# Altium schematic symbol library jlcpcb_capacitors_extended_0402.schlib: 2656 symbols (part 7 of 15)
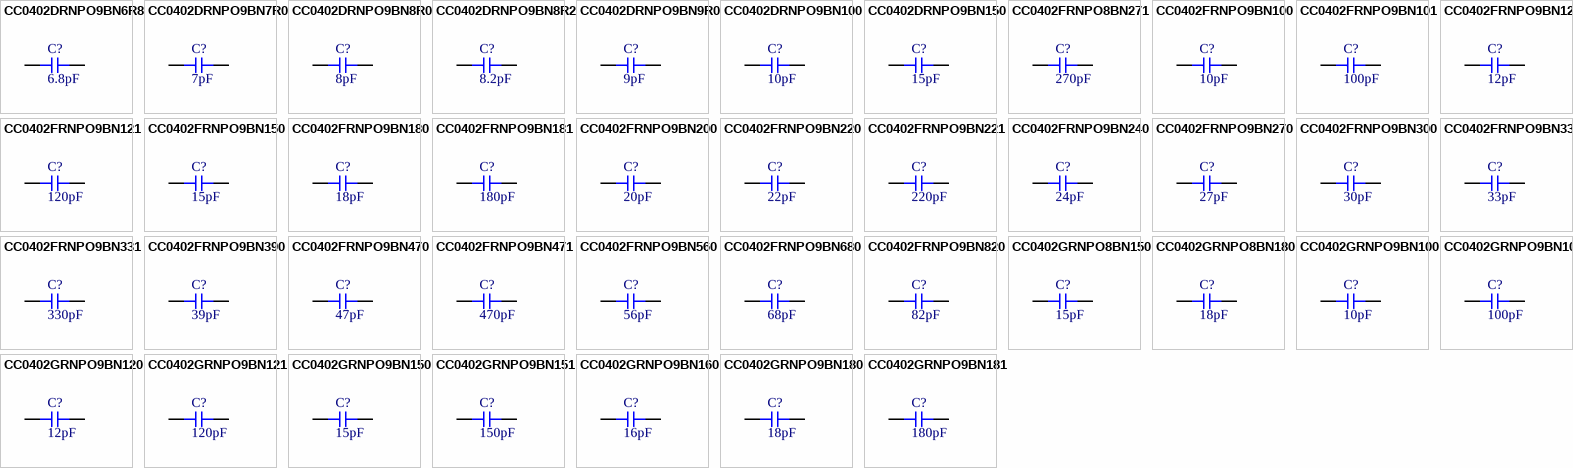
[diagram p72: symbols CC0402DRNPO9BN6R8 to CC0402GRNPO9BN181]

## CC0402FRNPO9BN180
designator C?  Capacitance: 18pF  (hidden comment: *)
Capacitor, Ceramic (MLCC), 18pF, ±1pF, 50V, NP0, ±1pF, SMD 0402; Manufacturer: YAGEO; Manufacturer Part Number: CC0402FRNPO9BN180
footprint CAP-0402 (0402 (1005M) Capacitor)
pins: 1, 2

## CC0402FRNPO9BN181
designator C?  Capacitance: 180pF  (hidden comment: *)
Capacitor, Ceramic (MLCC), 180pF, ±1pF, 50V, NP0, ±1pF, SMD 0402; Manufacturer: YAGEO; Manufacturer Part Number: CC0402FRNPO9BN181
footprint CAP-0402 (0402 (1005M) Capacitor)
pins: 1, 2

## CC0402FRNPO9BN200
designator C?  Capacitance: 20pF  (hidden comment: *)
Capacitor, Ceramic (MLCC), 20pF, ±1%, 50V, NP0, ±1%, SMD 0402; Manufacturer: YAGEO; Manufacturer Part Number: CC0402FRNPO9BN200
footprint CAP-0402 (0402 (1005M) Capacitor)
pins: 1, 2

## CC0402FRNPO9BN220
designator C?  Capacitance: 22pF  (hidden comment: *)
Capacitor, Ceramic (MLCC), 22pF, ±1%, 50V, NP0, ±1%, SMD 0402; Manufacturer: YAGEO; Manufacturer Part Number: CC0402FRNPO9BN220
footprint CAP-0402 (0402 (1005M) Capacitor)
pins: 1, 2

## CC0402FRNPO9BN221
designator C?  Capacitance: 220pF  (hidden comment: *)
Capacitor, Ceramic (MLCC), 220pF, ±1%, 50V, NP0, ±1%, SMD 0402; Manufacturer: YAGEO; Manufacturer Part Number: CC0402FRNPO9BN221
footprint CAP-0402 (0402 (1005M) Capacitor)
pins: 1, 2

## CC0402FRNPO9BN240
designator C?  Capacitance: 24pF  (hidden comment: *)
Capacitor, Ceramic (MLCC), 24pF, ±1pF, 50V, NP0, ±1pF, SMD 0402; Manufacturer: YAGEO; Manufacturer Part Number: CC0402FRNPO9BN240
footprint CAP-0402 (0402 (1005M) Capacitor)
pins: 1, 2

## CC0402FRNPO9BN270
designator C?  Capacitance: 27pF  (hidden comment: *)
Capacitor, Ceramic (MLCC), 27pF, ±1%, 50V, NP0, ±1%, SMD 0402; Manufacturer: YAGEO; Manufacturer Part Number: CC0402FRNPO9BN270
footprint CAP-0402 (0402 (1005M) Capacitor)
pins: 1, 2

## CC0402FRNPO9BN300
designator C?  Capacitance: 30pF  (hidden comment: *)
Capacitor, Ceramic (MLCC), 30pF, ±1%, 50V, NP0, ±1%, SMD 0402; Manufacturer: YAGEO; Manufacturer Part Number: CC0402FRNPO9BN300
footprint CAP-0402 (0402 (1005M) Capacitor)
pins: 1, 2

## CC0402FRNPO9BN330
designator C?  Capacitance: 33pF  (hidden comment: *)
Capacitor, Ceramic (MLCC), 33pF, ±1%, 50V, NP0, ±1%, SMD 0402; Manufacturer: YAGEO; Manufacturer Part Number: CC0402FRNPO9BN330
footprint CAP-0402 (0402 (1005M) Capacitor)
pins: 1, 2

## CC0402FRNPO9BN331
designator C?  Capacitance: 330pF  (hidden comment: *)
Capacitor, Ceramic (MLCC), 330pF, ±1pF, 50V, NP0, ±1pF, SMD 0402; Manufacturer: YAGEO; Manufacturer Part Number: CC0402FRNPO9BN331
footprint CAP-0402 (0402 (1005M) Capacitor)
pins: 1, 2

## CC0402FRNPO9BN390
designator C?  Capacitance: 39pF  (hidden comment: *)
Capacitor, Ceramic (MLCC), 39pF, ±1%, 50V, NP0, ±1%, SMD 0402; Manufacturer: YAGEO; Manufacturer Part Number: CC0402FRNPO9BN390
footprint CAP-0402 (0402 (1005M) Capacitor)
pins: 1, 2

## CC0402FRNPO9BN470
designator C?  Capacitance: 47pF  (hidden comment: *)
Capacitor, Ceramic (MLCC), 47pF, ±1%, 50V, NP0, ±1%, SMD 0402; Manufacturer: YAGEO; Manufacturer Part Number: CC0402FRNPO9BN470
footprint CAP-0402 (0402 (1005M) Capacitor)
pins: 1, 2

## CC0402FRNPO9BN471
designator C?  Capacitance: 470pF  (hidden comment: *)
Capacitor, Ceramic (MLCC), 470pF, ±1%, 50V, NP0, ±1%, SMD 0402; Manufacturer: YAGEO; Manufacturer Part Number: CC0402FRNPO9BN471
footprint CAP-0402 (0402 (1005M) Capacitor)
pins: 1, 2

## CC0402FRNPO9BN560
designator C?  Capacitance: 56pF  (hidden comment: *)
Capacitor, Ceramic (MLCC), 56pF, ±1%, 50V, NP0, ±1%, SMD 0402; Manufacturer: YAGEO; Manufacturer Part Number: CC0402FRNPO9BN560
footprint CAP-0402 (0402 (1005M) Capacitor)
pins: 1, 2

## CC0402FRNPO9BN680
designator C?  Capacitance: 68pF  (hidden comment: *)
Capacitor, Ceramic (MLCC), 68pF, ±1%, 50V, NP0, ±1%, SMD 0402; Manufacturer: YAGEO; Manufacturer Part Number: CC0402FRNPO9BN680
footprint CAP-0402 (0402 (1005M) Capacitor)
pins: 1, 2

## CC0402FRNPO9BN820
designator C?  Capacitance: 82pF  (hidden comment: *)
Capacitor, Ceramic (MLCC), 82pF, ±1%, 50V, NP0, ±1%, SMD 0402; Manufacturer: YAGEO; Manufacturer Part Number: CC0402FRNPO9BN820
footprint CAP-0402 (0402 (1005M) Capacitor)
pins: 1, 2

## CC0402GRNPO8BN150
designator C?  Capacitance: 15pF  (hidden comment: *)
Capacitor, Ceramic (MLCC), 15pF, ±2%, 25V, NP0, ±2%, SMD 0402; Manufacturer: YAGEO; Manufacturer Part Number: CC0402GRNPO8BN150
footprint CAP-0402 (0402 (1005M) Capacitor)
pins: 1, 2

## CC0402GRNPO8BN180
designator C?  Capacitance: 18pF  (hidden comment: *)
Capacitor, Ceramic (MLCC), 18pF, ±2%, 25V, NP0, ±2%, SMD 0402; Manufacturer: YAGEO; Manufacturer Part Number: CC0402GRNPO8BN180
footprint CAP-0402 (0402 (1005M) Capacitor)
pins: 1, 2

## CC0402GRNPO9BN100
designator C?  Capacitance: 10pF  (hidden comment: *)
Capacitor, Ceramic (MLCC), 10pF, ±2%, 50V, NP0, ±2%, SMD 0402; Manufacturer: YAGEO; Manufacturer Part Number: CC0402GRNPO9BN100
footprint CAP-0402 (0402 (1005M) Capacitor)
pins: 1, 2

## CC0402GRNPO9BN101
designator C?  Capacitance: 100pF  (hidden comment: *)
Capacitor, Ceramic (MLCC), 100pF, ±2%, 50V, NP0, ±2%, SMD 0402; Manufacturer: YAGEO; Manufacturer Part Number: CC0402GRNPO9BN101
footprint CAP-0402 (0402 (1005M) Capacitor)
pins: 1, 2

## CC0402GRNPO9BN120
designator C?  Capacitance: 12pF  (hidden comment: *)
Capacitor, Ceramic (MLCC), 12pF, ±2%, 50V, NP0, ±2%, SMD 0402; Manufacturer: YAGEO; Manufacturer Part Number: CC0402GRNPO9BN120
footprint CAP-0402 (0402 (1005M) Capacitor)
pins: 1, 2

## CC0402GRNPO9BN121
designator C?  Capacitance: 120pF  (hidden comment: *)
Capacitor, Ceramic (MLCC), 120pF, ±2%, 50V, NP0, ±2%, SMD 0402; Manufacturer: YAGEO; Manufacturer Part Number: CC0402GRNPO9BN121
footprint CAP-0402 (0402 (1005M) Capacitor)
pins: 1, 2

## CC0402GRNPO9BN150
designator C?  Capacitance: 15pF  (hidden comment: *)
Capacitor, Ceramic (MLCC), 15pF, ±2%, 50V, NP0, ±2%, SMD 0402; Manufacturer: YAGEO; Manufacturer Part Number: CC0402GRNPO9BN150
footprint CAP-0402 (0402 (1005M) Capacitor)
pins: 1, 2

## CC0402GRNPO9BN151
designator C?  Capacitance: 150pF  (hidden comment: *)
Capacitor, Ceramic (MLCC), 150pF, ±2%, 50V, NP0, ±2%, SMD 0402; Manufacturer: YAGEO; Manufacturer Part Number: CC0402GRNPO9BN151
footprint CAP-0402 (0402 (1005M) Capacitor)
pins: 1, 2

## CC0402GRNPO9BN160
designator C?  Capacitance: 16pF  (hidden comment: *)
Capacitor, Ceramic (MLCC), 16pF, ±2%, 50V, NP0, ±2%, SMD 0402; Manufacturer: YAGEO; Manufacturer Part Number: CC0402GRNPO9BN160
footprint CAP-0402 (0402 (1005M) Capacitor)
pins: 1, 2

## CC0402GRNPO9BN180
designator C?  Capacitance: 18pF  (hidden comment: *)
Capacitor, Ceramic (MLCC), 18pF, ±2%, 50V, NP0, ±2%, SMD 0402; Manufacturer: YAGEO; Manufacturer Part Number: CC0402GRNPO9BN180
footprint CAP-0402 (0402 (1005M) Capacitor)
pins: 1, 2

## CC0402GRNPO9BN181
designator C?  Capacitance: 180pF  (hidden comment: *)
Capacitor, Ceramic (MLCC), 180pF, ±2%, 50V, NP0, ±2%, SMD 0402; Manufacturer: YAGEO; Manufacturer Part Number: CC0402GRNPO9BN181
footprint CAP-0402 (0402 (1005M) Capacitor)
pins: 1, 2

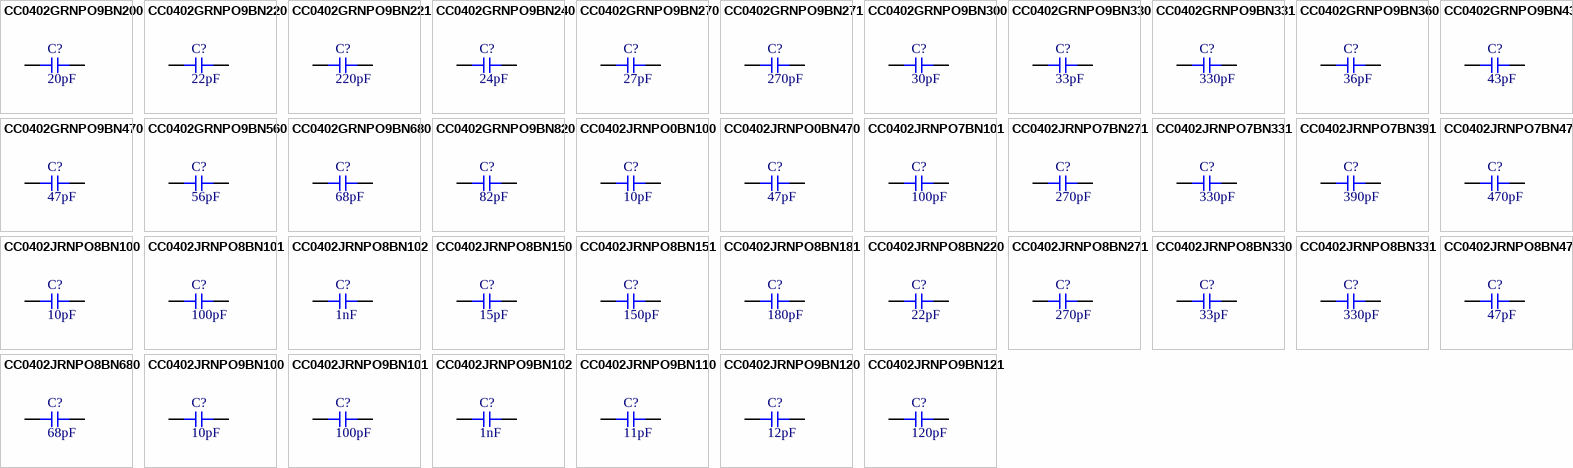
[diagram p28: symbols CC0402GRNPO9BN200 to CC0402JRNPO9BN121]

## CC0402GRNPO9BN200
designator C?  Capacitance: 20pF  (hidden comment: *)
Capacitor, Ceramic (MLCC), 20pF, ±2%, 50V, NP0, ±2%, SMD 0402; Manufacturer: YAGEO; Manufacturer Part Number: CC0402GRNPO9BN200
footprint CAP-0402 (0402 (1005M) Capacitor)
pins: 1, 2

## CC0402GRNPO9BN220
designator C?  Capacitance: 22pF  (hidden comment: *)
Capacitor, Ceramic (MLCC), 22pF, ±2%, 50V, NP0, ±2%, SMD 0402; Manufacturer: YAGEO; Manufacturer Part Number: CC0402GRNPO9BN220
footprint CAP-0402 (0402 (1005M) Capacitor)
pins: 1, 2

## CC0402GRNPO9BN221
designator C?  Capacitance: 220pF  (hidden comment: *)
Capacitor, Ceramic (MLCC), 220pF, ±2%, 50V, NP0, ±2%, SMD 0402; Manufacturer: YAGEO; Manufacturer Part Number: CC0402GRNPO9BN221
footprint CAP-0402 (0402 (1005M) Capacitor)
pins: 1, 2

## CC0402GRNPO9BN240
designator C?  Capacitance: 24pF  (hidden comment: *)
Capacitor, Ceramic (MLCC), 24pF, ±2%, 50V, NP0, ±2%, SMD 0402; Manufacturer: YAGEO; Manufacturer Part Number: CC0402GRNPO9BN240
footprint CAP-0402 (0402 (1005M) Capacitor)
pins: 1, 2

## CC0402GRNPO9BN270
designator C?  Capacitance: 27pF  (hidden comment: *)
Capacitor, Ceramic (MLCC), 27pF, ±2%, 50V, NP0, ±2%, SMD 0402; Manufacturer: YAGEO; Manufacturer Part Number: CC0402GRNPO9BN270
footprint CAP-0402 (0402 (1005M) Capacitor)
pins: 1, 2

## CC0402GRNPO9BN271
designator C?  Capacitance: 270pF  (hidden comment: *)
Capacitor, Ceramic (MLCC), 270pF, ±2%, 50V, NP0, ±2%, SMD 0402; Manufacturer: YAGEO; Manufacturer Part Number: CC0402GRNPO9BN271
footprint CAP-0402 (0402 (1005M) Capacitor)
pins: 1, 2

## CC0402GRNPO9BN300
designator C?  Capacitance: 30pF  (hidden comment: *)
Capacitor, Ceramic (MLCC), 30pF, ±2%, 50V, NP0, ±2%, SMD 0402; Manufacturer: YAGEO; Manufacturer Part Number: CC0402GRNPO9BN300
footprint CAP-0402 (0402 (1005M) Capacitor)
pins: 1, 2

## CC0402GRNPO9BN330
designator C?  Capacitance: 33pF  (hidden comment: *)
Capacitor, Ceramic (MLCC), 33pF, ±2%, 50V, NP0, ±2%, SMD 0402; Manufacturer: YAGEO; Manufacturer Part Number: CC0402GRNPO9BN330
footprint CAP-0402 (0402 (1005M) Capacitor)
pins: 1, 2

## CC0402GRNPO9BN331
designator C?  Capacitance: 330pF  (hidden comment: *)
Capacitor, Ceramic (MLCC), 330pF, ±2%, 50V, NP0, ±2%, SMD 0402; Manufacturer: YAGEO; Manufacturer Part Number: CC0402GRNPO9BN331
footprint CAP-0402 (0402 (1005M) Capacitor)
pins: 1, 2

## CC0402GRNPO9BN360
designator C?  Capacitance: 36pF  (hidden comment: *)
Capacitor, Ceramic (MLCC), 36pF, ±2%, 50V, NP0, ±2%, SMD 0402; Manufacturer: YAGEO; Manufacturer Part Number: CC0402GRNPO9BN360
footprint CAP-0402 (0402 (1005M) Capacitor)
pins: 1, 2

## CC0402GRNPO9BN430
designator C?  Capacitance: 43pF  (hidden comment: *)
Capacitor, Ceramic (MLCC), 43pF, ±2%, 50V, NP0, ±2%, SMD 0402; Manufacturer: YAGEO; Manufacturer Part Number: CC0402GRNPO9BN430
footprint CAP-0402 (0402 (1005M) Capacitor)
pins: 1, 2

## CC0402GRNPO9BN470
designator C?  Capacitance: 47pF  (hidden comment: *)
Capacitor, Ceramic (MLCC), 47pF, ±2%, 50V, NP0, ±2%, SMD 0402; Manufacturer: YAGEO; Manufacturer Part Number: CC0402GRNPO9BN470
footprint CAP-0402 (0402 (1005M) Capacitor)
pins: 1, 2

## CC0402GRNPO9BN560
designator C?  Capacitance: 56pF  (hidden comment: *)
Capacitor, Ceramic (MLCC), 56pF, ±2%, 50V, NP0, ±2%, SMD 0402; Manufacturer: YAGEO; Manufacturer Part Number: CC0402GRNPO9BN560
footprint CAP-0402 (0402 (1005M) Capacitor)
pins: 1, 2

## CC0402GRNPO9BN680
designator C?  Capacitance: 68pF  (hidden comment: *)
Capacitor, Ceramic (MLCC), 68pF, ±2%, 50V, NP0, ±2%, SMD 0402; Manufacturer: YAGEO; Manufacturer Part Number: CC0402GRNPO9BN680
footprint CAP-0402 (0402 (1005M) Capacitor)
pins: 1, 2

## CC0402GRNPO9BN820
designator C?  Capacitance: 82pF  (hidden comment: *)
Capacitor, Ceramic (MLCC), 82pF, ±2%, 50V, NP0, ±2%, SMD 0402; Manufacturer: YAGEO; Manufacturer Part Number: CC0402GRNPO9BN820
footprint CAP-0402 (0402 (1005M) Capacitor)
pins: 1, 2

## CC0402JRNPO0BN100
designator C?  Capacitance: 10pF  (hidden comment: *)
Capacitor, Ceramic (MLCC), 10pF, ±5%, 100V, NP0, ±5%, SMD 0402; Manufacturer: YAGEO; Manufacturer Part Number: CC0402JRNPO0BN100
footprint CAP-0402 (0402 (1005M) Capacitor)
pins: 1, 2

## CC0402JRNPO0BN470
designator C?  Capacitance: 47pF  (hidden comment: *)
Capacitor, Ceramic (MLCC), 47pF, ±5%, 100V, NP0, ±5%, SMD 0402; Manufacturer: YAGEO; Manufacturer Part Number: CC0402JRNPO0BN470
footprint CAP-0402 (0402 (1005M) Capacitor)
pins: 1, 2

## CC0402JRNPO7BN101
designator C?  Capacitance: 100pF  (hidden comment: *)
Capacitor, Ceramic (MLCC), 100pF, ±5%, 16V, NP0, ±5%, SMD 0402; Manufacturer: YAGEO; Manufacturer Part Number: CC0402JRNPO7BN101
footprint CAP-0402 (0402 (1005M) Capacitor)
pins: 1, 2

## CC0402JRNPO7BN271
designator C?  Capacitance: 270pF  (hidden comment: *)
Capacitor, Ceramic (MLCC), 270pF, ±5%, 16V, NP0, ±5%, SMD 0402; Manufacturer: YAGEO; Manufacturer Part Number: CC0402JRNPO7BN271
footprint CAP-0402 (0402 (1005M) Capacitor)
pins: 1, 2

## CC0402JRNPO7BN331
designator C?  Capacitance: 330pF  (hidden comment: *)
Capacitor, Ceramic (MLCC), 330pF, ±5%, 16V, NP0, ±5%, SMD 0402; Manufacturer: YAGEO; Manufacturer Part Number: CC0402JRNPO7BN331
footprint CAP-0402 (0402 (1005M) Capacitor)
pins: 1, 2

## CC0402JRNPO7BN391
designator C?  Capacitance: 390pF  (hidden comment: *)
Capacitor, Ceramic (MLCC), 390pF, ±5%, 16V, NP0, ±5%, SMD 0402; Manufacturer: YAGEO; Manufacturer Part Number: CC0402JRNPO7BN391
footprint CAP-0402 (0402 (1005M) Capacitor)
pins: 1, 2

## CC0402JRNPO7BN471
designator C?  Capacitance: 470pF  (hidden comment: *)
Capacitor, Ceramic (MLCC), 470pF, ±5%, 16V, NP0, ±5%, SMD 0402; Manufacturer: YAGEO; Manufacturer Part Number: CC0402JRNPO7BN471
footprint CAP-0402 (0402 (1005M) Capacitor)
pins: 1, 2

## CC0402JRNPO8BN100
designator C?  Capacitance: 10pF  (hidden comment: *)
Capacitor, Ceramic (MLCC), 10pF, ±5%, 25V, NP0, ±5%, SMD 0402; Manufacturer: YAGEO; Manufacturer Part Number: CC0402JRNPO8BN100
footprint CAP-0402 (0402 (1005M) Capacitor)
pins: 1, 2

## CC0402JRNPO8BN101
designator C?  Capacitance: 100pF  (hidden comment: *)
Capacitor, Ceramic (MLCC), 100pF, ±5%, 25V, NP0, ±5%, SMD 0402; Manufacturer: YAGEO; Manufacturer Part Number: CC0402JRNPO8BN101
footprint CAP-0402 (0402 (1005M) Capacitor)
pins: 1, 2

## CC0402JRNPO8BN102
designator C?  Capacitance: 1nF  (hidden comment: *)
Capacitor, Ceramic (MLCC), 1nF, ±5%, 25V, NP0, ±5%, SMD 0402; Manufacturer: YAGEO; Manufacturer Part Number: CC0402JRNPO8BN102
footprint CAP-0402 (0402 (1005M) Capacitor)
pins: 1, 2

## CC0402JRNPO8BN150
designator C?  Capacitance: 15pF  (hidden comment: *)
Capacitor, Ceramic (MLCC), 15pF, ±5%, 25V, NP0, ±5%, SMD 0402; Manufacturer: YAGEO; Manufacturer Part Number: CC0402JRNPO8BN150
footprint CAP-0402 (0402 (1005M) Capacitor)
pins: 1, 2

## CC0402JRNPO8BN151
designator C?  Capacitance: 150pF  (hidden comment: *)
Capacitor, Ceramic (MLCC), 150pF, ±5%, 25V, NP0, ±5%, SMD 0402; Manufacturer: YAGEO; Manufacturer Part Number: CC0402JRNPO8BN151
footprint CAP-0402 (0402 (1005M) Capacitor)
pins: 1, 2

## CC0402JRNPO8BN181
designator C?  Capacitance: 180pF  (hidden comment: *)
Capacitor, Ceramic (MLCC), 180pF, ±5%, 25V, NP0, ±5%, SMD 0402; Manufacturer: YAGEO; Manufacturer Part Number: CC0402JRNPO8BN181
footprint CAP-0402 (0402 (1005M) Capacitor)
pins: 1, 2

## CC0402JRNPO8BN220
designator C?  Capacitance: 22pF  (hidden comment: *)
Capacitor, Ceramic (MLCC), 22pF, ±5%, 25V, NP0, ±5%, SMD 0402; Manufacturer: YAGEO; Manufacturer Part Number: CC0402JRNPO8BN220
footprint CAP-0402 (0402 (1005M) Capacitor)
pins: 1, 2

## CC0402JRNPO8BN271
designator C?  Capacitance: 270pF  (hidden comment: *)
Capacitor, Ceramic (MLCC), 270pF, ±5%, 25V, NP0, ±5%, SMD 0402; Manufacturer: YAGEO; Manufacturer Part Number: CC0402JRNPO8BN271
footprint CAP-0402 (0402 (1005M) Capacitor)
pins: 1, 2

## CC0402JRNPO8BN330
designator C?  Capacitance: 33pF  (hidden comment: *)
Capacitor, Ceramic (MLCC), 33pF, ±5%, 25V, NP0, ±5%, SMD 0402; Manufacturer: YAGEO; Manufacturer Part Number: CC0402JRNPO8BN330
footprint CAP-0402 (0402 (1005M) Capacitor)
pins: 1, 2

## CC0402JRNPO8BN331
designator C?  Capacitance: 330pF  (hidden comment: *)
Capacitor, Ceramic (MLCC), 330pF, ±5%, 25V, NP0, ±5%, SMD 0402; Manufacturer: YAGEO; Manufacturer Part Number: CC0402JRNPO8BN331
footprint CAP-0402 (0402 (1005M) Capacitor)
pins: 1, 2

## CC0402JRNPO8BN470
designator C?  Capacitance: 47pF  (hidden comment: *)
Capacitor, Ceramic (MLCC), 47pF, ±5%, 25V, NP0, ±5%, SMD 0402; Manufacturer: YAGEO; Manufacturer Part Number: CC0402JRNPO8BN470
footprint CAP-0402 (0402 (1005M) Capacitor)
pins: 1, 2

## CC0402JRNPO8BN680
designator C?  Capacitance: 68pF  (hidden comment: *)
Capacitor, Ceramic (MLCC), 68pF, ±5%, 25V, NP0, ±5%, SMD 0402; Manufacturer: YAGEO; Manufacturer Part Number: CC0402JRNPO8BN680
footprint CAP-0402 (0402 (1005M) Capacitor)
pins: 1, 2

## CC0402JRNPO9BN100
designator C?  Capacitance: 10pF  (hidden comment: *)
Capacitor, Ceramic (MLCC), 10pF, ±5%, 50V, NP0, ±5%, SMD 0402; Manufacturer: YAGEO; Manufacturer Part Number: CC0402JRNPO9BN100
footprint CAP-0402 (0402 (1005M) Capacitor)
pins: 1, 2

## CC0402JRNPO9BN101
designator C?  Capacitance: 100pF  (hidden comment: *)
Capacitor, Ceramic (MLCC), 100pF, ±5%, 50V, NP0, ±5%, SMD 0402; Manufacturer: YAGEO; Manufacturer Part Number: CC0402JRNPO9BN101
footprint CAP-0402 (0402 (1005M) Capacitor)
pins: 1, 2

## CC0402JRNPO9BN102
designator C?  Capacitance: 1nF  (hidden comment: *)
Capacitor, Ceramic (MLCC), 1nF, ±5%, 50V, NP0, ±5%, SMD 0402; Manufacturer: YAGEO; Manufacturer Part Number: CC0402JRNPO9BN102
footprint CAP-0402 (0402 (1005M) Capacitor)
pins: 1, 2

## CC0402JRNPO9BN110
designator C?  Capacitance: 11pF  (hidden comment: *)
Capacitor, Ceramic (MLCC), 11pF, ±5%, 50V, NP0, ±5%, SMD 0402; Manufacturer: YAGEO; Manufacturer Part Number: CC0402JRNPO9BN110
footprint CAP-0402 (0402 (1005M) Capacitor)
pins: 1, 2

## CC0402JRNPO9BN120
designator C?  Capacitance: 12pF  (hidden comment: *)
Capacitor, Ceramic (MLCC), 12pF, ±5%, 50V, NP0, ±5%, SMD 0402; Manufacturer: YAGEO; Manufacturer Part Number: CC0402JRNPO9BN120
footprint CAP-0402 (0402 (1005M) Capacitor)
pins: 1, 2

## CC0402JRNPO9BN121
designator C?  Capacitance: 120pF  (hidden comment: *)
Capacitor, Ceramic (MLCC), 120pF, ±5%, 50V, NP0, ±5%, SMD 0402; Manufacturer: YAGEO; Manufacturer Part Number: CC0402JRNPO9BN121
footprint CAP-0402 (0402 (1005M) Capacitor)
pins: 1, 2

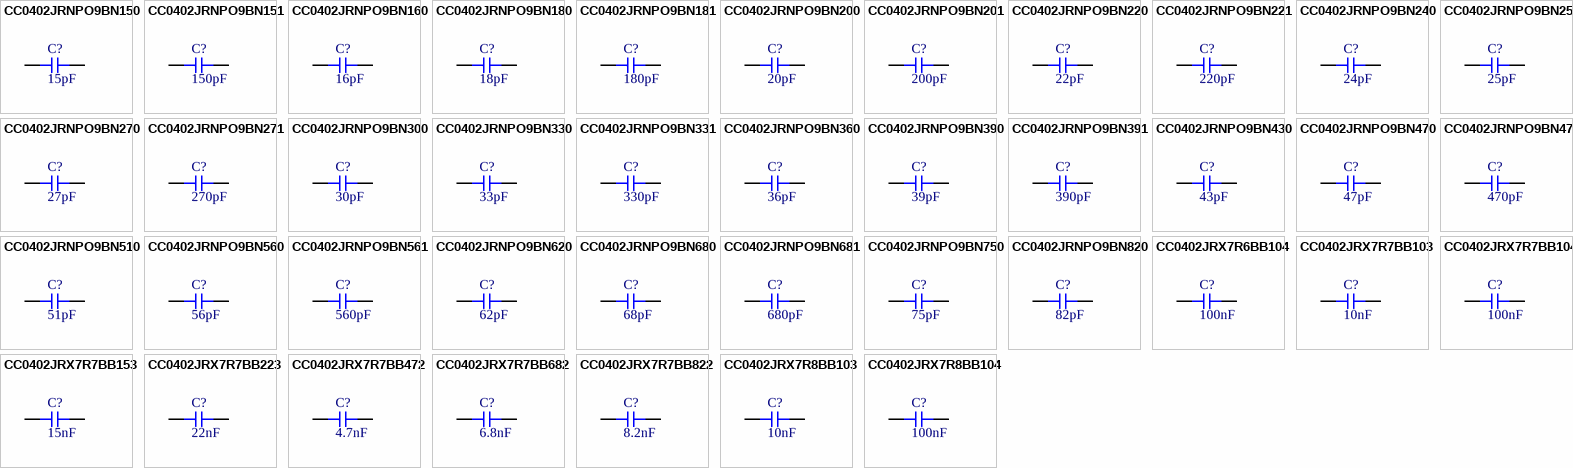
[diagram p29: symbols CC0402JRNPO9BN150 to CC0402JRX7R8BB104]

## CC0402JRNPO9BN150
designator C?  Capacitance: 15pF  (hidden comment: *)
Capacitor, Ceramic (MLCC), 15pF, ±5%, 50V, NP0, ±5%, SMD 0402; Manufacturer: YAGEO; Manufacturer Part Number: CC0402JRNPO9BN150
footprint CAP-0402 (0402 (1005M) Capacitor)
pins: 1, 2

## CC0402JRNPO9BN151
designator C?  Capacitance: 150pF  (hidden comment: *)
Capacitor, Ceramic (MLCC), 150pF, ±5%, 50V, NP0, ±5%, SMD 0402; Manufacturer: YAGEO; Manufacturer Part Number: CC0402JRNPO9BN151
footprint CAP-0402 (0402 (1005M) Capacitor)
pins: 1, 2

## CC0402JRNPO9BN160
designator C?  Capacitance: 16pF  (hidden comment: *)
Capacitor, Ceramic (MLCC), 16pF, ±5%, 50V, NP0, ±5%, SMD 0402; Manufacturer: YAGEO; Manufacturer Part Number: CC0402JRNPO9BN160
footprint CAP-0402 (0402 (1005M) Capacitor)
pins: 1, 2

## CC0402JRNPO9BN180
designator C?  Capacitance: 18pF  (hidden comment: *)
Capacitor, Ceramic (MLCC), 18pF, ±5%, 50V, NP0, ±5%, SMD 0402; Manufacturer: YAGEO; Manufacturer Part Number: CC0402JRNPO9BN180
footprint CAP-0402 (0402 (1005M) Capacitor)
pins: 1, 2

## CC0402JRNPO9BN181
designator C?  Capacitance: 180pF  (hidden comment: *)
Capacitor, Ceramic (MLCC), 180pF, ±5%, 50V, NP0, ±5%, SMD 0402; Manufacturer: YAGEO; Manufacturer Part Number: CC0402JRNPO9BN181
footprint CAP-0402 (0402 (1005M) Capacitor)
pins: 1, 2

## CC0402JRNPO9BN200
designator C?  Capacitance: 20pF  (hidden comment: *)
Capacitor, Ceramic (MLCC), 20pF, ±5%, 50V, NP0, ±5%, SMD 0402; Manufacturer: YAGEO; Manufacturer Part Number: CC0402JRNPO9BN200
footprint CAP-0402 (0402 (1005M) Capacitor)
pins: 1, 2

## CC0402JRNPO9BN201
designator C?  Capacitance: 200pF  (hidden comment: *)
Capacitor, Ceramic (MLCC), 200pF, ±5%, 50V, NP0, ±5%, SMD 0402; Manufacturer: YAGEO; Manufacturer Part Number: CC0402JRNPO9BN201
footprint CAP-0402 (0402 (1005M) Capacitor)
pins: 1, 2

## CC0402JRNPO9BN220
designator C?  Capacitance: 22pF  (hidden comment: *)
Capacitor, Ceramic (MLCC), 22pF, ±5%, 50V, NP0, ±5%, SMD 0402; Manufacturer: YAGEO; Manufacturer Part Number: CC0402JRNPO9BN220
footprint CAP-0402 (0402 (1005M) Capacitor)
pins: 1, 2

## CC0402JRNPO9BN221
designator C?  Capacitance: 220pF  (hidden comment: *)
Capacitor, Ceramic (MLCC), 220pF, ±5%, 50V, NP0, ±5%, SMD 0402; Manufacturer: YAGEO; Manufacturer Part Number: CC0402JRNPO9BN221
footprint CAP-0402 (0402 (1005M) Capacitor)
pins: 1, 2

## CC0402JRNPO9BN240
designator C?  Capacitance: 24pF  (hidden comment: *)
Capacitor, Ceramic (MLCC), 24pF, ±5%, 50V, NP0, ±5%, SMD 0402; Manufacturer: YAGEO; Manufacturer Part Number: CC0402JRNPO9BN240
footprint CAP-0402 (0402 (1005M) Capacitor)
pins: 1, 2

## CC0402JRNPO9BN250
designator C?  Capacitance: 25pF  (hidden comment: *)
Capacitor, Ceramic (MLCC), 25pF, ±5%, 50V, NP0, ±5%, SMD 0402; Manufacturer: YAGEO; Manufacturer Part Number: CC0402JRNPO9BN250
footprint CAP-0402 (0402 (1005M) Capacitor)
pins: 1, 2

## CC0402JRNPO9BN270
designator C?  Capacitance: 27pF  (hidden comment: *)
Capacitor, Ceramic (MLCC), 27pF, ±5%, 50V, NP0, ±5%, SMD 0402; Manufacturer: YAGEO; Manufacturer Part Number: CC0402JRNPO9BN270
footprint CAP-0402 (0402 (1005M) Capacitor)
pins: 1, 2

## CC0402JRNPO9BN271
designator C?  Capacitance: 270pF  (hidden comment: *)
Capacitor, Ceramic (MLCC), 270pF, ±5%, 50V, NP0, ±5%, SMD 0402; Manufacturer: YAGEO; Manufacturer Part Number: CC0402JRNPO9BN271
footprint CAP-0402 (0402 (1005M) Capacitor)
pins: 1, 2

## CC0402JRNPO9BN300
designator C?  Capacitance: 30pF  (hidden comment: *)
Capacitor, Ceramic (MLCC), 30pF, ±5%, 50V, NP0, ±5%, SMD 0402; Manufacturer: YAGEO; Manufacturer Part Number: CC0402JRNPO9BN300
footprint CAP-0402 (0402 (1005M) Capacitor)
pins: 1, 2

## CC0402JRNPO9BN330
designator C?  Capacitance: 33pF  (hidden comment: *)
Capacitor, Ceramic (MLCC), 33pF, ±5%, 50V, NP0, ±5%, SMD 0402; Manufacturer: YAGEO; Manufacturer Part Number: CC0402JRNPO9BN330
footprint CAP-0402 (0402 (1005M) Capacitor)
pins: 1, 2

## CC0402JRNPO9BN331
designator C?  Capacitance: 330pF  (hidden comment: *)
Capacitor, Ceramic (MLCC), 330pF, ±5%, 50V, NP0, ±5%, SMD 0402; Manufacturer: YAGEO; Manufacturer Part Number: CC0402JRNPO9BN331
footprint CAP-0402 (0402 (1005M) Capacitor)
pins: 1, 2

## CC0402JRNPO9BN360
designator C?  Capacitance: 36pF  (hidden comment: *)
Capacitor, Ceramic (MLCC), 36pF, ±5%, 50V, NP0, ±5%, SMD 0402; Manufacturer: YAGEO; Manufacturer Part Number: CC0402JRNPO9BN360
footprint CAP-0402 (0402 (1005M) Capacitor)
pins: 1, 2

## CC0402JRNPO9BN390
designator C?  Capacitance: 39pF  (hidden comment: *)
Capacitor, Ceramic (MLCC), 39pF, ±5%, 50V, NP0, ±5%, SMD 0402; Manufacturer: YAGEO; Manufacturer Part Number: CC0402JRNPO9BN390
footprint CAP-0402 (0402 (1005M) Capacitor)
pins: 1, 2

## CC0402JRNPO9BN391
designator C?  Capacitance: 390pF  (hidden comment: *)
Capacitor, Ceramic (MLCC), 390pF, ±5%, 50V, NP0, ±5%, SMD 0402; Manufacturer: YAGEO; Manufacturer Part Number: CC0402JRNPO9BN391
footprint CAP-0402 (0402 (1005M) Capacitor)
pins: 1, 2

## CC0402JRNPO9BN430
designator C?  Capacitance: 43pF  (hidden comment: *)
Capacitor, Ceramic (MLCC), 43pF, ±5%, 50V, NP0, ±5%, SMD 0402; Manufacturer: YAGEO; Manufacturer Part Number: CC0402JRNPO9BN430
footprint CAP-0402 (0402 (1005M) Capacitor)
pins: 1, 2

## CC0402JRNPO9BN470
designator C?  Capacitance: 47pF  (hidden comment: *)
Capacitor, Ceramic (MLCC), 47pF, ±5%, 50V, NP0, ±5%, SMD 0402; Manufacturer: YAGEO; Manufacturer Part Number: CC0402JRNPO9BN470
footprint CAP-0402 (0402 (1005M) Capacitor)
pins: 1, 2

## CC0402JRNPO9BN471
designator C?  Capacitance: 470pF  (hidden comment: *)
Capacitor, Ceramic (MLCC), 470pF, ±5%, 50V, NP0, ±5%, SMD 0402; Manufacturer: YAGEO; Manufacturer Part Number: CC0402JRNPO9BN471
footprint CAP-0402 (0402 (1005M) Capacitor)
pins: 1, 2

## CC0402JRNPO9BN510
designator C?  Capacitance: 51pF  (hidden comment: *)
Capacitor, Ceramic (MLCC), 51pF, ±5%, 50V, NP0, ±5%, SMD 0402; Manufacturer: YAGEO; Manufacturer Part Number: CC0402JRNPO9BN510
footprint CAP-0402 (0402 (1005M) Capacitor)
pins: 1, 2

## CC0402JRNPO9BN560
designator C?  Capacitance: 56pF  (hidden comment: *)
Capacitor, Ceramic (MLCC), 56pF, ±5%, 50V, NP0, ±5%, SMD 0402; Manufacturer: YAGEO; Manufacturer Part Number: CC0402JRNPO9BN560
footprint CAP-0402 (0402 (1005M) Capacitor)
pins: 1, 2

## CC0402JRNPO9BN561
designator C?  Capacitance: 560pF  (hidden comment: *)
Capacitor, Ceramic (MLCC), 560pF, ±5%, 50V, NP0, ±5%, SMD 0402; Manufacturer: YAGEO; Manufacturer Part Number: CC0402JRNPO9BN561
footprint CAP-0402 (0402 (1005M) Capacitor)
pins: 1, 2

## CC0402JRNPO9BN620
designator C?  Capacitance: 62pF  (hidden comment: *)
Capacitor, Ceramic (MLCC), 62pF, ±5%, 50V, NP0, ±5%, SMD 0402; Manufacturer: YAGEO; Manufacturer Part Number: CC0402JRNPO9BN620
footprint CAP-0402 (0402 (1005M) Capacitor)
pins: 1, 2

## CC0402JRNPO9BN680
designator C?  Capacitance: 68pF  (hidden comment: *)
Capacitor, Ceramic (MLCC), 68pF, ±5%, 50V, NP0, ±5%, SMD 0402; Manufacturer: YAGEO; Manufacturer Part Number: CC0402JRNPO9BN680
footprint CAP-0402 (0402 (1005M) Capacitor)
pins: 1, 2

## CC0402JRNPO9BN681
designator C?  Capacitance: 680pF  (hidden comment: *)
Capacitor, Ceramic (MLCC), 680pF, ±5%, 50V, NP0, ±5%, SMD 0402; Manufacturer: YAGEO; Manufacturer Part Number: CC0402JRNPO9BN681
footprint CAP-0402 (0402 (1005M) Capacitor)
pins: 1, 2

## CC0402JRNPO9BN750
designator C?  Capacitance: 75pF  (hidden comment: *)
Capacitor, Ceramic (MLCC), 75pF, ±5%, 50V, NP0, ±5%, SMD 0402; Manufacturer: YAGEO; Manufacturer Part Number: CC0402JRNPO9BN750
footprint CAP-0402 (0402 (1005M) Capacitor)
pins: 1, 2

## CC0402JRNPO9BN820
designator C?  Capacitance: 82pF  (hidden comment: *)
Capacitor, Ceramic (MLCC), 82pF, ±5%, 50V, NP0, ±5%, SMD 0402; Manufacturer: YAGEO; Manufacturer Part Number: CC0402JRNPO9BN820
footprint CAP-0402 (0402 (1005M) Capacitor)
pins: 1, 2

## CC0402JRX7R6BB104
designator C?  Capacitance: 100nF  (hidden comment: *)
Capacitor, Ceramic (MLCC), 100nF, ±5%, 10V, X7R, ±5%, SMD 0402; Manufacturer: YAGEO; Manufacturer Part Number: CC0402JRX7R6BB104
footprint CAP-0402 (0402 (1005M) Capacitor)
pins: 1, 2

## CC0402JRX7R7BB103
designator C?  Capacitance: 10nF  (hidden comment: *)
Capacitor, Ceramic (MLCC), 10nF, ±5%, 16V, X7R, ±5%, SMD 0402; Manufacturer: YAGEO; Manufacturer Part Number: CC0402JRX7R7BB103
footprint CAP-0402 (0402 (1005M) Capacitor)
pins: 1, 2

## CC0402JRX7R7BB104
designator C?  Capacitance: 100nF  (hidden comment: *)
Capacitor, Ceramic (MLCC), 100nF, ±5%, 16V, X7R, ±5%, SMD 0402; Manufacturer: YAGEO; Manufacturer Part Number: CC0402JRX7R7BB104
footprint CAP-0402 (0402 (1005M) Capacitor)
pins: 1, 2

## CC0402JRX7R7BB153
designator C?  Capacitance: 15nF  (hidden comment: *)
Capacitor, Ceramic (MLCC), 15nF, ±5%, 16V, X7R, ±5%, SMD 0402; Manufacturer: YAGEO; Manufacturer Part Number: CC0402JRX7R7BB153
footprint CAP-0402 (0402 (1005M) Capacitor)
pins: 1, 2

## CC0402JRX7R7BB223
designator C?  Capacitance: 22nF  (hidden comment: *)
Capacitor, Ceramic (MLCC), 22nF, ±5%, 16V, X7R, ±5%, SMD 0402; Manufacturer: YAGEO; Manufacturer Part Number: CC0402JRX7R7BB223
footprint CAP-0402 (0402 (1005M) Capacitor)
pins: 1, 2

## CC0402JRX7R7BB472
designator C?  Capacitance: 4.7nF  (hidden comment: *)
Capacitor, Ceramic (MLCC), 4.7nF, ±5%, 16V, X7R, ±5%, SMD 0402; Manufacturer: YAGEO; Manufacturer Part Number: CC0402JRX7R7BB472
footprint CAP-0402 (0402 (1005M) Capacitor)
pins: 1, 2

## CC0402JRX7R7BB682
designator C?  Capacitance: 6.8nF  (hidden comment: *)
Capacitor, Ceramic (MLCC), 6.8nF, ±5%, 16V, X7R, ±5%, SMD 0402; Manufacturer: YAGEO; Manufacturer Part Number: CC0402JRX7R7BB682
footprint CAP-0402 (0402 (1005M) Capacitor)
pins: 1, 2

## CC0402JRX7R7BB822
designator C?  Capacitance: 8.2nF  (hidden comment: *)
Capacitor, Ceramic (MLCC), 8.2nF, ±5%, 16V, X7R, ±5%, SMD 0402; Manufacturer: YAGEO; Manufacturer Part Number: CC0402JRX7R7BB822
footprint CAP-0402 (0402 (1005M) Capacitor)
pins: 1, 2

## CC0402JRX7R8BB103
designator C?  Capacitance: 10nF  (hidden comment: *)
Capacitor, Ceramic (MLCC), 10nF, ±5%, 25V, X7R, ±5%, SMD 0402; Manufacturer: YAGEO; Manufacturer Part Number: CC0402JRX7R8BB103
footprint CAP-0402 (0402 (1005M) Capacitor)
pins: 1, 2

## CC0402JRX7R8BB104
designator C?  Capacitance: 100nF  (hidden comment: *)
Capacitor, Ceramic (MLCC), 100nF, ±5%, 25V, X7R, ±5%, SMD 0402; Manufacturer: YAGEO; Manufacturer Part Number: CC0402JRX7R8BB104
footprint CAP-0402 (0402 (1005M) Capacitor)
pins: 1, 2

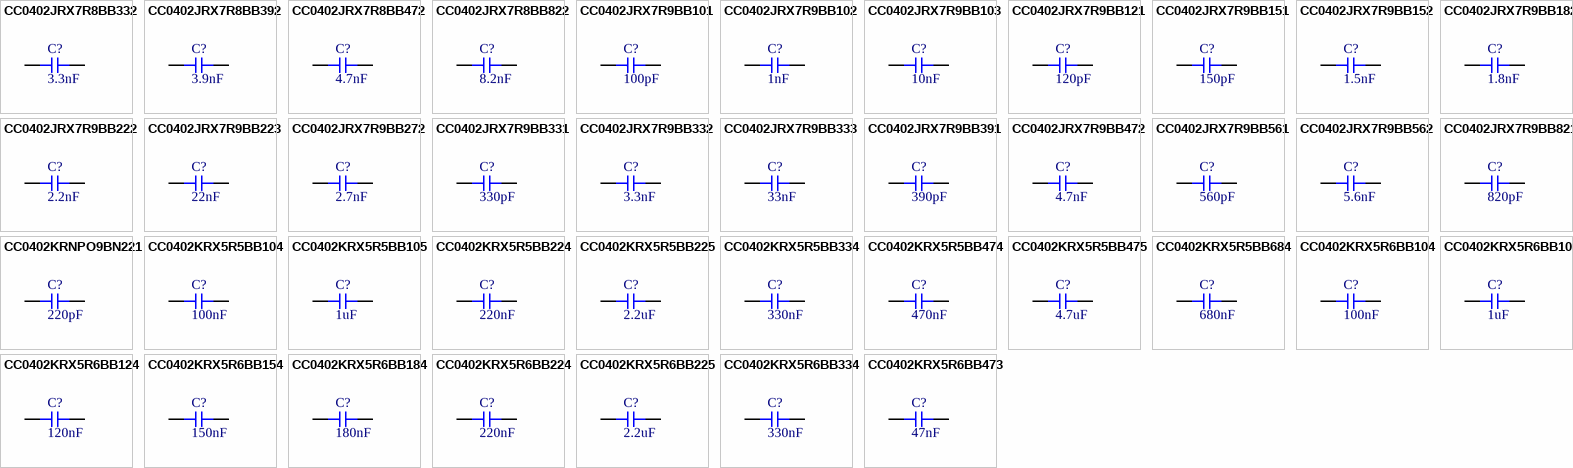
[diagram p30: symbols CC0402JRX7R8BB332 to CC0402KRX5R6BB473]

## CC0402JRX7R8BB332
designator C?  Capacitance: 3.3nF  (hidden comment: *)
Capacitor, Ceramic (MLCC), 3.3nF, ±5%, 25V, X7R, ±5%, SMD 0402; Manufacturer: YAGEO; Manufacturer Part Number: CC0402JRX7R8BB332
footprint CAP-0402 (0402 (1005M) Capacitor)
pins: 1, 2

## CC0402JRX7R8BB392
designator C?  Capacitance: 3.9nF  (hidden comment: *)
Capacitor, Ceramic (MLCC), 3.9nF, ±5%, 25V, X7R, ±5%, SMD 0402; Manufacturer: YAGEO; Manufacturer Part Number: CC0402JRX7R8BB392
footprint CAP-0402 (0402 (1005M) Capacitor)
pins: 1, 2

## CC0402JRX7R8BB472
designator C?  Capacitance: 4.7nF  (hidden comment: *)
Capacitor, Ceramic (MLCC), 4.7nF, ±5%, 25V, X7R, ±5%, SMD 0402; Manufacturer: YAGEO; Manufacturer Part Number: CC0402JRX7R8BB472
footprint CAP-0402 (0402 (1005M) Capacitor)
pins: 1, 2

## CC0402JRX7R8BB822
designator C?  Capacitance: 8.2nF  (hidden comment: *)
Capacitor, Ceramic (MLCC), 8.2nF, ±5%, 25V, X7R, ±5%, SMD 0402; Manufacturer: YAGEO; Manufacturer Part Number: CC0402JRX7R8BB822
footprint CAP-0402 (0402 (1005M) Capacitor)
pins: 1, 2

## CC0402JRX7R9BB101
designator C?  Capacitance: 100pF  (hidden comment: *)
Capacitor, Ceramic (MLCC), 100pF, ±5%, 50V, X7R, ±5%, SMD 0402; Manufacturer: YAGEO; Manufacturer Part Number: CC0402JRX7R9BB101
footprint CAP-0402 (0402 (1005M) Capacitor)
pins: 1, 2

## CC0402JRX7R9BB102
designator C?  Capacitance: 1nF  (hidden comment: *)
Capacitor, Ceramic (MLCC), 1nF, ±5%, 50V, X7R, ±5%, SMD 0402; Manufacturer: YAGEO; Manufacturer Part Number: CC0402JRX7R9BB102
footprint CAP-0402 (0402 (1005M) Capacitor)
pins: 1, 2

## CC0402JRX7R9BB103
designator C?  Capacitance: 10nF  (hidden comment: *)
Capacitor, Ceramic (MLCC), 10nF, ±5%, 50V, X7R, ±5%, SMD 0402; Manufacturer: YAGEO; Manufacturer Part Number: CC0402JRX7R9BB103
footprint CAP-0402 (0402 (1005M) Capacitor)
pins: 1, 2

## CC0402JRX7R9BB121
designator C?  Capacitance: 120pF  (hidden comment: *)
Capacitor, Ceramic (MLCC), 120pF, ±5%, 50V, X7R, ±5%, SMD 0402; Manufacturer: YAGEO; Manufacturer Part Number: CC0402JRX7R9BB121
footprint CAP-0402 (0402 (1005M) Capacitor)
pins: 1, 2

## CC0402JRX7R9BB151
designator C?  Capacitance: 150pF  (hidden comment: *)
Capacitor, Ceramic (MLCC), 150pF, ±5%, 50V, X7R, ±5%, SMD 0402; Manufacturer: YAGEO; Manufacturer Part Number: CC0402JRX7R9BB151
footprint CAP-0402 (0402 (1005M) Capacitor)
pins: 1, 2

## CC0402JRX7R9BB152
designator C?  Capacitance: 1.5nF  (hidden comment: *)
Capacitor, Ceramic (MLCC), 1.5nF, ±5%, 50V, X7R, ±5%, SMD 0402; Manufacturer: YAGEO; Manufacturer Part Number: CC0402JRX7R9BB152
footprint CAP-0402 (0402 (1005M) Capacitor)
pins: 1, 2

## CC0402JRX7R9BB182
designator C?  Capacitance: 1.8nF  (hidden comment: *)
Capacitor, Ceramic (MLCC), 1.8nF, ±5%, 50V, X7R, ±5%, SMD 0402; Manufacturer: YAGEO; Manufacturer Part Number: CC0402JRX7R9BB182
footprint CAP-0402 (0402 (1005M) Capacitor)
pins: 1, 2

## CC0402JRX7R9BB222
designator C?  Capacitance: 2.2nF  (hidden comment: *)
Capacitor, Ceramic (MLCC), 2.2nF, ±5%, 50V, X7R, ±5%, SMD 0402; Manufacturer: YAGEO; Manufacturer Part Number: CC0402JRX7R9BB222
footprint CAP-0402 (0402 (1005M) Capacitor)
pins: 1, 2

## CC0402JRX7R9BB223
designator C?  Capacitance: 22nF  (hidden comment: *)
Capacitor, Ceramic (MLCC), 22nF, ±5%, 50V, X7R, ±5%, SMD 0402; Manufacturer: YAGEO; Manufacturer Part Number: CC0402JRX7R9BB223
footprint CAP-0402 (0402 (1005M) Capacitor)
pins: 1, 2

## CC0402JRX7R9BB272
designator C?  Capacitance: 2.7nF  (hidden comment: *)
Capacitor, Ceramic (MLCC), 2.7nF, ±5%, 50V, X7R, ±5%, SMD 0402; Manufacturer: YAGEO; Manufacturer Part Number: CC0402JRX7R9BB272
footprint CAP-0402 (0402 (1005M) Capacitor)
pins: 1, 2

## CC0402JRX7R9BB331
designator C?  Capacitance: 330pF  (hidden comment: *)
Capacitor, Ceramic (MLCC), 330pF, ±5%, 50V, X7R, ±5%, SMD 0402; Manufacturer: YAGEO; Manufacturer Part Number: CC0402JRX7R9BB331
footprint CAP-0402 (0402 (1005M) Capacitor)
pins: 1, 2

## CC0402JRX7R9BB332
designator C?  Capacitance: 3.3nF  (hidden comment: *)
Capacitor, Ceramic (MLCC), 3.3nF, ±5%, 50V, X7R, ±5%, SMD 0402; Manufacturer: YAGEO; Manufacturer Part Number: CC0402JRX7R9BB332
footprint CAP-0402 (0402 (1005M) Capacitor)
pins: 1, 2

## CC0402JRX7R9BB333
designator C?  Capacitance: 33nF  (hidden comment: *)
Capacitor, Ceramic (MLCC), 33nF, ±5%, 50V, X7R, ±5%, SMD 0402; Manufacturer: YAGEO; Manufacturer Part Number: CC0402JRX7R9BB333
footprint CAP-0402 (0402 (1005M) Capacitor)
pins: 1, 2

## CC0402JRX7R9BB391
designator C?  Capacitance: 390pF  (hidden comment: *)
Capacitor, Ceramic (MLCC), 390pF, ±5%, 50V, X7R, ±5%, SMD 0402; Manufacturer: YAGEO; Manufacturer Part Number: CC0402JRX7R9BB391
footprint CAP-0402 (0402 (1005M) Capacitor)
pins: 1, 2

## CC0402JRX7R9BB472
designator C?  Capacitance: 4.7nF  (hidden comment: *)
Capacitor, Ceramic (MLCC), 4.7nF, ±5%, 50V, X7R, ±5%, SMD 0402; Manufacturer: YAGEO; Manufacturer Part Number: CC0402JRX7R9BB472
footprint CAP-0402 (0402 (1005M) Capacitor)
pins: 1, 2

## CC0402JRX7R9BB561
designator C?  Capacitance: 560pF  (hidden comment: *)
Capacitor, Ceramic (MLCC), 560pF, ±5%, 50V, X7R, ±5%, SMD 0402; Manufacturer: YAGEO; Manufacturer Part Number: CC0402JRX7R9BB561
footprint CAP-0402 (0402 (1005M) Capacitor)
pins: 1, 2

## CC0402JRX7R9BB562
designator C?  Capacitance: 5.6nF  (hidden comment: *)
Capacitor, Ceramic (MLCC), 5.6nF, ±5%, 50V, X7R, ±5%, SMD 0402; Manufacturer: YAGEO; Manufacturer Part Number: CC0402JRX7R9BB562
footprint CAP-0402 (0402 (1005M) Capacitor)
pins: 1, 2

## CC0402JRX7R9BB821
designator C?  Capacitance: 820pF  (hidden comment: *)
Capacitor, Ceramic (MLCC), 820pF, ±5%, 50V, X7R, ±5%, SMD 0402; Manufacturer: YAGEO; Manufacturer Part Number: CC0402JRX7R9BB821
footprint CAP-0402 (0402 (1005M) Capacitor)
pins: 1, 2

## CC0402KRNPO9BN221
designator C?  Capacitance: 220pF  (hidden comment: *)
Capacitor, Ceramic (MLCC), 220pF, ±10%, 50V, NP0, ±10%, SMD 0402; Manufacturer: YAGEO; Manufacturer Part Number: CC0402KRNPO9BN221
footprint CAP-0402 (0402 (1005M) Capacitor)
pins: 1, 2

## CC0402KRX5R5BB104
designator C?  Capacitance: 100nF  (hidden comment: *)
Capacitor, Ceramic (MLCC), 100nF, ±10%, 6.3V, X5R, ±10%, SMD 0402; Manufacturer: YAGEO; Manufacturer Part Number: CC0402KRX5R5BB104
footprint CAP-0402 (0402 (1005M) Capacitor)
pins: 1, 2

## CC0402KRX5R5BB105
designator C?  Capacitance: 1uF  (hidden comment: *)
Capacitor, Ceramic (MLCC), 1uF, ±10%, 6.3V, X5R, ±10%, SMD 0402; Manufacturer: YAGEO; Manufacturer Part Number: CC0402KRX5R5BB105
footprint CAP-0402 (0402 (1005M) Capacitor)
pins: 1, 2

## CC0402KRX5R5BB224
designator C?  Capacitance: 220nF  (hidden comment: *)
Capacitor, Ceramic (MLCC), 220nF, ±10%, 6.3V, X5R, ±10%, SMD 0402; Manufacturer: YAGEO; Manufacturer Part Number: CC0402KRX5R5BB224
footprint CAP-0402 (0402 (1005M) Capacitor)
pins: 1, 2

## CC0402KRX5R5BB225
designator C?  Capacitance: 2.2uF  (hidden comment: *)
Capacitor, Ceramic (MLCC), 2.2uF, ±10%, 6.3V, X5R, ±10%, SMD 0402; Manufacturer: YAGEO; Manufacturer Part Number: CC0402KRX5R5BB225
footprint CAP-0402 (0402 (1005M) Capacitor)
pins: 1, 2

## CC0402KRX5R5BB334
designator C?  Capacitance: 330nF  (hidden comment: *)
Capacitor, Ceramic (MLCC), 330nF, ±10%, 6.3V, X5R, ±10%, SMD 0402; Manufacturer: YAGEO; Manufacturer Part Number: CC0402KRX5R5BB334
footprint CAP-0402 (0402 (1005M) Capacitor)
pins: 1, 2

## CC0402KRX5R5BB474
designator C?  Capacitance: 470nF  (hidden comment: *)
Capacitor, Ceramic (MLCC), 470nF, ±10%, 6.3V, X5R, ±10%, SMD 0402; Manufacturer: YAGEO; Manufacturer Part Number: CC0402KRX5R5BB474
footprint CAP-0402 (0402 (1005M) Capacitor)
pins: 1, 2

## CC0402KRX5R5BB475
designator C?  Capacitance: 4.7uF  (hidden comment: *)
Capacitor, Ceramic (MLCC), 4.7uF, ±10%, 6.3V, X5R, ±10%, SMD 0402; Manufacturer: YAGEO; Manufacturer Part Number: CC0402KRX5R5BB475
footprint CAP-0402 (0402 (1005M) Capacitor)
pins: 1, 2

## CC0402KRX5R5BB684
designator C?  Capacitance: 680nF  (hidden comment: *)
Capacitor, Ceramic (MLCC), 680nF, ±10%, 6.3V, X5R, ±10%, SMD 0402; Manufacturer: YAGEO; Manufacturer Part Number: CC0402KRX5R5BB684
footprint CAP-0402 (0402 (1005M) Capacitor)
pins: 1, 2

## CC0402KRX5R6BB104
designator C?  Capacitance: 100nF  (hidden comment: *)
Capacitor, Ceramic (MLCC), 100nF, ±10%, 10V, X5R, ±10%, SMD 0402; Manufacturer: YAGEO; Manufacturer Part Number: CC0402KRX5R6BB104
footprint CAP-0402 (0402 (1005M) Capacitor)
pins: 1, 2

## CC0402KRX5R6BB105
designator C?  Capacitance: 1uF  (hidden comment: *)
Capacitor, Ceramic (MLCC), 1uF, ±10%, 10V, X5R, ±10%, SMD 0402; Manufacturer: YAGEO; Manufacturer Part Number: CC0402KRX5R6BB105
footprint CAP-0402 (0402 (1005M) Capacitor)
pins: 1, 2

## CC0402KRX5R6BB124
designator C?  Capacitance: 120nF  (hidden comment: *)
Capacitor, Ceramic (MLCC), 120nF, ±10%, 10V, X5R, ±10%, SMD 0402; Manufacturer: YAGEO; Manufacturer Part Number: CC0402KRX5R6BB124
footprint CAP-0402 (0402 (1005M) Capacitor)
pins: 1, 2

## CC0402KRX5R6BB154
designator C?  Capacitance: 150nF  (hidden comment: *)
Capacitor, Ceramic (MLCC), 150nF, ±10%, 10V, X5R, ±10%, SMD 0402; Manufacturer: YAGEO; Manufacturer Part Number: CC0402KRX5R6BB154
footprint CAP-0402 (0402 (1005M) Capacitor)
pins: 1, 2

## CC0402KRX5R6BB184
designator C?  Capacitance: 180nF  (hidden comment: *)
Capacitor, Ceramic (MLCC), 180nF, ±10%, 10V, X5R, ±10%, SMD 0402; Manufacturer: YAGEO; Manufacturer Part Number: CC0402KRX5R6BB184
footprint CAP-0402 (0402 (1005M) Capacitor)
pins: 1, 2

## CC0402KRX5R6BB224
designator C?  Capacitance: 220nF  (hidden comment: *)
Capacitor, Ceramic (MLCC), 220nF, ±10%, 10V, X5R, ±10%, SMD 0402; Manufacturer: YAGEO; Manufacturer Part Number: CC0402KRX5R6BB224
footprint CAP-0402 (0402 (1005M) Capacitor)
pins: 1, 2

## CC0402KRX5R6BB225
designator C?  Capacitance: 2.2uF  (hidden comment: *)
Capacitor, Ceramic (MLCC), 2.2uF, ±10%, 10V, X5R, ±10%, SMD 0402; Manufacturer: YAGEO; Manufacturer Part Number: CC0402KRX5R6BB225
footprint CAP-0402 (0402 (1005M) Capacitor)
pins: 1, 2

## CC0402KRX5R6BB334
designator C?  Capacitance: 330nF  (hidden comment: *)
Capacitor, Ceramic (MLCC), 330nF, ±10%, 10V, X5R, ±10%, SMD 0402; Manufacturer: YAGEO; Manufacturer Part Number: CC0402KRX5R6BB334
footprint CAP-0402 (0402 (1005M) Capacitor)
pins: 1, 2

## CC0402KRX5R6BB473
designator C?  Capacitance: 47nF  (hidden comment: *)
Capacitor, Ceramic (MLCC), 47nF, ±10%, 10V, X5R, ±10%, SMD 0402; Manufacturer: YAGEO; Manufacturer Part Number: CC0402KRX5R6BB473
footprint CAP-0402 (0402 (1005M) Capacitor)
pins: 1, 2

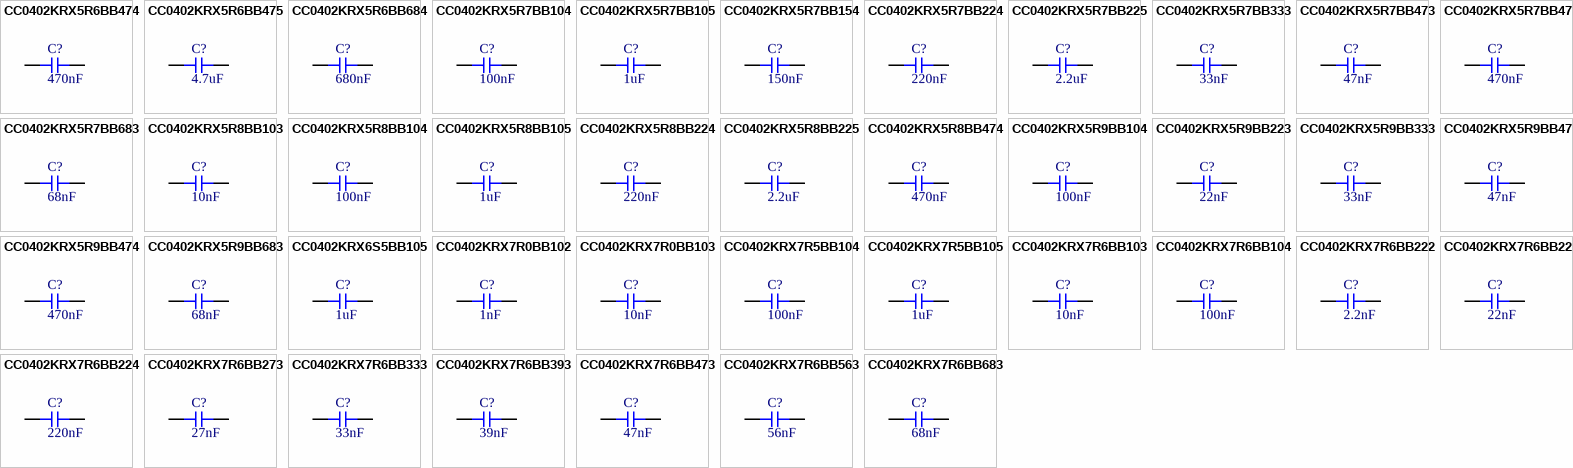
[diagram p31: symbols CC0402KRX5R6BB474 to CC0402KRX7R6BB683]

## CC0402KRX5R6BB474
designator C?  Capacitance: 470nF  (hidden comment: *)
Capacitor, Ceramic (MLCC), 470nF, ±10%, 10V, X5R, ±10%, SMD 0402; Manufacturer: YAGEO; Manufacturer Part Number: CC0402KRX5R6BB474
footprint CAP-0402 (0402 (1005M) Capacitor)
pins: 1, 2

## CC0402KRX5R6BB475
designator C?  Capacitance: 4.7uF  (hidden comment: *)
Capacitor, Ceramic (MLCC), 4.7uF, ±10%, 10V, X5R, ±10%, SMD 0402; Manufacturer: YAGEO; Manufacturer Part Number: CC0402KRX5R6BB475
footprint CAP-0402 (0402 (1005M) Capacitor)
pins: 1, 2

## CC0402KRX5R6BB684
designator C?  Capacitance: 680nF  (hidden comment: *)
Capacitor, Ceramic (MLCC), 680nF, ±10%, 10V, X5R, ±10%, SMD 0402; Manufacturer: YAGEO; Manufacturer Part Number: CC0402KRX5R6BB684
footprint CAP-0402 (0402 (1005M) Capacitor)
pins: 1, 2

## CC0402KRX5R7BB104
designator C?  Capacitance: 100nF  (hidden comment: *)
Capacitor, Ceramic (MLCC), 100nF, ±10%, 16V, X5R, ±10%, SMD 0402; Manufacturer: YAGEO; Manufacturer Part Number: CC0402KRX5R7BB104
footprint CAP-0402 (0402 (1005M) Capacitor)
pins: 1, 2

## CC0402KRX5R7BB105
designator C?  Capacitance: 1uF  (hidden comment: *)
Capacitor, Ceramic (MLCC), 1uF, ±10%, 16V, X5R, ±10%, SMD 0402; Manufacturer: YAGEO; Manufacturer Part Number: CC0402KRX5R7BB105
footprint CAP-0402 (0402 (1005M) Capacitor)
pins: 1, 2

## CC0402KRX5R7BB154
designator C?  Capacitance: 150nF  (hidden comment: *)
Capacitor, Ceramic (MLCC), 150nF, ±10%, 16V, X5R, ±10%, SMD 0402; Manufacturer: YAGEO; Manufacturer Part Number: CC0402KRX5R7BB154
footprint CAP-0402 (0402 (1005M) Capacitor)
pins: 1, 2

## CC0402KRX5R7BB224
designator C?  Capacitance: 220nF  (hidden comment: *)
Capacitor, Ceramic (MLCC), 220nF, ±10%, 16V, X5R, ±10%, SMD 0402; Manufacturer: YAGEO; Manufacturer Part Number: CC0402KRX5R7BB224
footprint CAP-0402 (0402 (1005M) Capacitor)
pins: 1, 2

## CC0402KRX5R7BB225
designator C?  Capacitance: 2.2uF  (hidden comment: *)
Capacitor, Ceramic (MLCC), 2.2uF, ±10%, 16V, X5R, ±10%, SMD 0402; Manufacturer: YAGEO; Manufacturer Part Number: CC0402KRX5R7BB225
footprint CAP-0402 (0402 (1005M) Capacitor)
pins: 1, 2

## CC0402KRX5R7BB333
designator C?  Capacitance: 33nF  (hidden comment: *)
Capacitor, Ceramic (MLCC), 33nF, ±10%, 16V, X5R, ±10%, SMD 0402; Manufacturer: YAGEO; Manufacturer Part Number: CC0402KRX5R7BB333
footprint CAP-0402 (0402 (1005M) Capacitor)
pins: 1, 2

## CC0402KRX5R7BB473
designator C?  Capacitance: 47nF  (hidden comment: *)
Capacitor, Ceramic (MLCC), 47nF, ±10%, 16V, X5R, ±10%, SMD 0402; Manufacturer: YAGEO; Manufacturer Part Number: CC0402KRX5R7BB473
footprint CAP-0402 (0402 (1005M) Capacitor)
pins: 1, 2

## CC0402KRX5R7BB474
designator C?  Capacitance: 470nF  (hidden comment: *)
Capacitor, Ceramic (MLCC), 470nF, ±10%, 16V, X5R, ±10%, SMD 0402; Manufacturer: YAGEO; Manufacturer Part Number: CC0402KRX5R7BB474
footprint CAP-0402 (0402 (1005M) Capacitor)
pins: 1, 2

## CC0402KRX5R7BB683
designator C?  Capacitance: 68nF  (hidden comment: *)
Capacitor, Ceramic (MLCC), 68nF, ±10%, 16V, X5R, ±10%, SMD 0402; Manufacturer: YAGEO; Manufacturer Part Number: CC0402KRX5R7BB683
footprint CAP-0402 (0402 (1005M) Capacitor)
pins: 1, 2

## CC0402KRX5R8BB103
designator C?  Capacitance: 10nF  (hidden comment: *)
Capacitor, Ceramic (MLCC), 10nF, ±10%, 25V, X5R, ±10%, SMD 0402; Manufacturer: YAGEO; Manufacturer Part Number: CC0402KRX5R8BB103
footprint CAP-0402 (0402 (1005M) Capacitor)
pins: 1, 2

## CC0402KRX5R8BB104
designator C?  Capacitance: 100nF  (hidden comment: *)
Capacitor, Ceramic (MLCC), 100nF, ±10%, 25V, X5R, ±10%, SMD 0402; Manufacturer: YAGEO; Manufacturer Part Number: CC0402KRX5R8BB104
footprint CAP-0402 (0402 (1005M) Capacitor)
pins: 1, 2

## CC0402KRX5R8BB105
designator C?  Capacitance: 1uF  (hidden comment: *)
Capacitor, Ceramic (MLCC), 1uF, ±10%, 25V, X5R, ±10%, SMD 0402; Manufacturer: YAGEO; Manufacturer Part Number: CC0402KRX5R8BB105
footprint CAP-0402 (0402 (1005M) Capacitor)
pins: 1, 2

## CC0402KRX5R8BB224
designator C?  Capacitance: 220nF  (hidden comment: *)
Capacitor, Ceramic (MLCC), 220nF, ±10%, 25V, X5R, ±10%, SMD 0402; Manufacturer: YAGEO; Manufacturer Part Number: CC0402KRX5R8BB224
footprint CAP-0402 (0402 (1005M) Capacitor)
pins: 1, 2

## CC0402KRX5R8BB225
designator C?  Capacitance: 2.2uF  (hidden comment: *)
Capacitor, Ceramic (MLCC), 2.2uF, ±10%, 25V, X5R, ±10%, SMD 0402; Manufacturer: YAGEO; Manufacturer Part Number: CC0402KRX5R8BB225
footprint CAP-0402 (0402 (1005M) Capacitor)
pins: 1, 2

## CC0402KRX5R8BB474
designator C?  Capacitance: 470nF  (hidden comment: *)
Capacitor, Ceramic (MLCC), 470nF, ±10%, 25V, X5R, ±10%, SMD 0402; Manufacturer: YAGEO; Manufacturer Part Number: CC0402KRX5R8BB474
footprint CAP-0402 (0402 (1005M) Capacitor)
pins: 1, 2

## CC0402KRX5R9BB104
designator C?  Capacitance: 100nF  (hidden comment: *)
Capacitor, Ceramic (MLCC), 100nF, ±10%, 50V, X5R, ±10%, SMD 0402; Manufacturer: YAGEO; Manufacturer Part Number: CC0402KRX5R9BB104
footprint CAP-0402 (0402 (1005M) Capacitor)
pins: 1, 2

## CC0402KRX5R9BB223
designator C?  Capacitance: 22nF  (hidden comment: *)
Capacitor, Ceramic (MLCC), 22nF, ±10%, 50V, X5R, ±10%, SMD 0402; Manufacturer: YAGEO; Manufacturer Part Number: CC0402KRX5R9BB223
footprint CAP-0402 (0402 (1005M) Capacitor)
pins: 1, 2

## CC0402KRX5R9BB333
designator C?  Capacitance: 33nF  (hidden comment: *)
Capacitor, Ceramic (MLCC), 33nF, ±10%, 50V, X5R, ±10%, SMD 0402; Manufacturer: YAGEO; Manufacturer Part Number: CC0402KRX5R9BB333
footprint CAP-0402 (0402 (1005M) Capacitor)
pins: 1, 2

## CC0402KRX5R9BB473
designator C?  Capacitance: 47nF  (hidden comment: *)
Capacitor, Ceramic (MLCC), 47nF, ±10%, 50V, X5R, ±10%, SMD 0402; Manufacturer: YAGEO; Manufacturer Part Number: CC0402KRX5R9BB473
footprint CAP-0402 (0402 (1005M) Capacitor)
pins: 1, 2

## CC0402KRX5R9BB474
designator C?  Capacitance: 470nF  (hidden comment: *)
Capacitor, Ceramic (MLCC), 470nF, ±10%, 50V, X5R, ±10%, SMD 0402; Manufacturer: YAGEO; Manufacturer Part Number: CC0402KRX5R9BB474
footprint CAP-0402 (0402 (1005M) Capacitor)
pins: 1, 2

## CC0402KRX5R9BB683
designator C?  Capacitance: 68nF  (hidden comment: *)
Capacitor, Ceramic (MLCC), 68nF, ±10%, 50V, X5R, ±10%, SMD 0402; Manufacturer: YAGEO; Manufacturer Part Number: CC0402KRX5R9BB683
footprint CAP-0402 (0402 (1005M) Capacitor)
pins: 1, 2

## CC0402KRX6S5BB105
designator C?  Capacitance: 1uF  (hidden comment: *)
Capacitor, Ceramic (MLCC), 1uF, ±10%, 6.3V, X6S, ±10%, SMD 0402; Manufacturer: YAGEO; Manufacturer Part Number: CC0402KRX6S5BB105
footprint CAP-0402 (0402 (1005M) Capacitor)
pins: 1, 2

## CC0402KRX7R0BB102
designator C?  Capacitance: 1nF  (hidden comment: *)
Capacitor, Ceramic (MLCC), 1nF, ±10%, 100V, X7R, ±10%, SMD 0402; Manufacturer: YAGEO; Manufacturer Part Number: CC0402KRX7R0BB102
footprint CAP-0402 (0402 (1005M) Capacitor)
pins: 1, 2

## CC0402KRX7R0BB103
designator C?  Capacitance: 10nF  (hidden comment: *)
Capacitor, Ceramic (MLCC), 10nF, ±10%, 100V, X7R, ±10%, SMD 0402; Manufacturer: YAGEO; Manufacturer Part Number: CC0402KRX7R0BB103
footprint CAP-0402 (0402 (1005M) Capacitor)
pins: 1, 2

## CC0402KRX7R5BB104
designator C?  Capacitance: 100nF  (hidden comment: *)
Capacitor, Ceramic (MLCC), 100nF, ±10%, 6.3V, X7R, ±10%, SMD 0402; Manufacturer: YAGEO; Manufacturer Part Number: CC0402KRX7R5BB104
footprint CAP-0402 (0402 (1005M) Capacitor)
pins: 1, 2

## CC0402KRX7R5BB105
designator C?  Capacitance: 1uF  (hidden comment: *)
Capacitor, Ceramic (MLCC), 1uF, ±10%, 6.3V, X7R, ±10%, SMD 0402; Manufacturer: YAGEO; Manufacturer Part Number: CC0402KRX7R5BB105
footprint CAP-0402 (0402 (1005M) Capacitor)
pins: 1, 2

## CC0402KRX7R6BB103
designator C?  Capacitance: 10nF  (hidden comment: *)
Capacitor, Ceramic (MLCC), 10nF, ±10%, 10V, X7R, ±10%, SMD 0402; Manufacturer: YAGEO; Manufacturer Part Number: CC0402KRX7R6BB103
footprint CAP-0402 (0402 (1005M) Capacitor)
pins: 1, 2

## CC0402KRX7R6BB104
designator C?  Capacitance: 100nF  (hidden comment: *)
Capacitor, Ceramic (MLCC), 100nF, ±10%, 10V, X7R, ±10%, SMD 0402; Manufacturer: YAGEO; Manufacturer Part Number: CC0402KRX7R6BB104
footprint CAP-0402 (0402 (1005M) Capacitor)
pins: 1, 2

## CC0402KRX7R6BB222
designator C?  Capacitance: 2.2nF  (hidden comment: *)
Capacitor, Ceramic (MLCC), 2.2nF, ±10%, 10V, X7R, ±10%, SMD 0402; Manufacturer: YAGEO; Manufacturer Part Number: CC0402KRX7R6BB222
footprint CAP-0402 (0402 (1005M) Capacitor)
pins: 1, 2

## CC0402KRX7R6BB223
designator C?  Capacitance: 22nF  (hidden comment: *)
Capacitor, Ceramic (MLCC), 22nF, ±10%, 10V, X7R, ±10%, SMD 0402; Manufacturer: YAGEO; Manufacturer Part Number: CC0402KRX7R6BB223
footprint CAP-0402 (0402 (1005M) Capacitor)
pins: 1, 2

## CC0402KRX7R6BB224
designator C?  Capacitance: 220nF  (hidden comment: *)
Capacitor, Ceramic (MLCC), 220nF, ±10%, 10V, X7R, ±10%, SMD 0402; Manufacturer: YAGEO; Manufacturer Part Number: CC0402KRX7R6BB224
footprint CAP-0402 (0402 (1005M) Capacitor)
pins: 1, 2

## CC0402KRX7R6BB273
designator C?  Capacitance: 27nF  (hidden comment: *)
Capacitor, Ceramic (MLCC), 27nF, ±10%, 10V, X7R, ±10%, SMD 0402; Manufacturer: YAGEO; Manufacturer Part Number: CC0402KRX7R6BB273
footprint CAP-0402 (0402 (1005M) Capacitor)
pins: 1, 2

## CC0402KRX7R6BB333
designator C?  Capacitance: 33nF  (hidden comment: *)
Capacitor, Ceramic (MLCC), 33nF, ±10%, 10V, X7R, ±10%, SMD 0402; Manufacturer: YAGEO; Manufacturer Part Number: CC0402KRX7R6BB333
footprint CAP-0402 (0402 (1005M) Capacitor)
pins: 1, 2

## CC0402KRX7R6BB393
designator C?  Capacitance: 39nF  (hidden comment: *)
Capacitor, Ceramic (MLCC), 39nF, ±10%, 10V, X7R, ±10%, SMD 0402; Manufacturer: YAGEO; Manufacturer Part Number: CC0402KRX7R6BB393
footprint CAP-0402 (0402 (1005M) Capacitor)
pins: 1, 2

## CC0402KRX7R6BB473
designator C?  Capacitance: 47nF  (hidden comment: *)
Capacitor, Ceramic (MLCC), 47nF, ±10%, 10V, X7R, ±10%, SMD 0402; Manufacturer: YAGEO; Manufacturer Part Number: CC0402KRX7R6BB473
footprint CAP-0402 (0402 (1005M) Capacitor)
pins: 1, 2

## CC0402KRX7R6BB563
designator C?  Capacitance: 56nF  (hidden comment: *)
Capacitor, Ceramic (MLCC), 56nF, ±10%, 10V, X7R, ±10%, SMD 0402; Manufacturer: YAGEO; Manufacturer Part Number: CC0402KRX7R6BB563
footprint CAP-0402 (0402 (1005M) Capacitor)
pins: 1, 2

## CC0402KRX7R6BB683
designator C?  Capacitance: 68nF  (hidden comment: *)
Capacitor, Ceramic (MLCC), 68nF, ±10%, 10V, X7R, ±10%, SMD 0402; Manufacturer: YAGEO; Manufacturer Part Number: CC0402KRX7R6BB683
footprint CAP-0402 (0402 (1005M) Capacitor)
pins: 1, 2

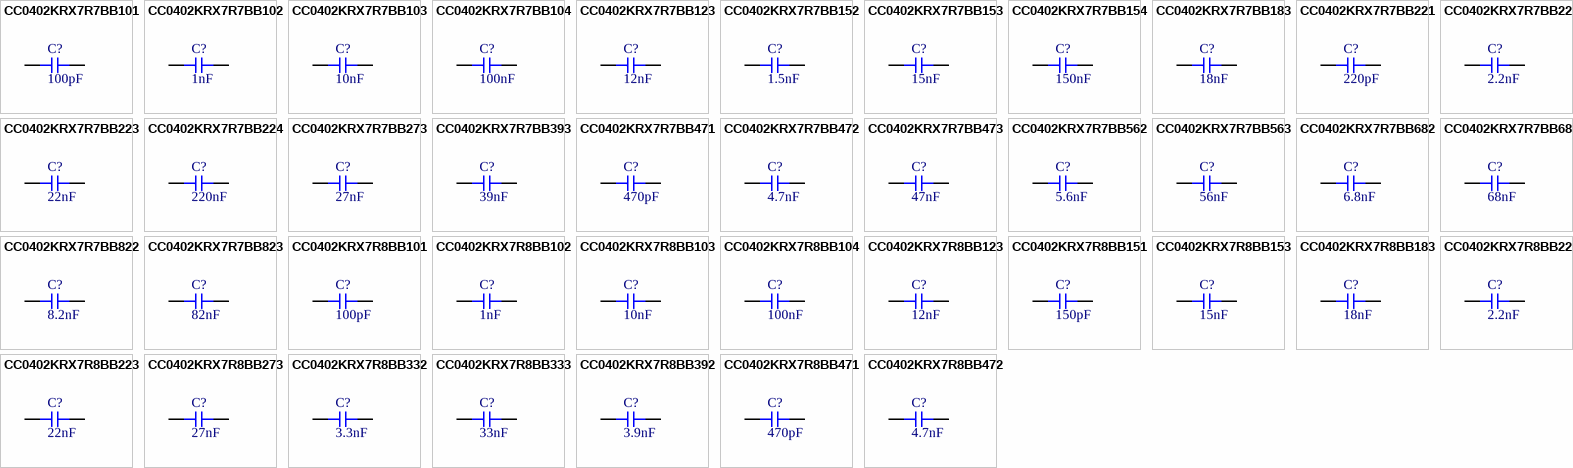
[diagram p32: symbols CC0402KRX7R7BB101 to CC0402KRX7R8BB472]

## CC0402KRX7R7BB101
designator C?  Capacitance: 100pF  (hidden comment: *)
Capacitor, Ceramic (MLCC), 100pF, ±10%, 16V, X7R, ±10%, SMD 0402; Manufacturer: YAGEO; Manufacturer Part Number: CC0402KRX7R7BB101
footprint CAP-0402 (0402 (1005M) Capacitor)
pins: 1, 2

## CC0402KRX7R7BB102
designator C?  Capacitance: 1nF  (hidden comment: *)
Capacitor, Ceramic (MLCC), 1nF, ±10%, 16V, X7R, ±10%, SMD 0402; Manufacturer: YAGEO; Manufacturer Part Number: CC0402KRX7R7BB102
footprint CAP-0402 (0402 (1005M) Capacitor)
pins: 1, 2

## CC0402KRX7R7BB103
designator C?  Capacitance: 10nF  (hidden comment: *)
Capacitor, Ceramic (MLCC), 10nF, ±10%, 16V, X7R, ±10%, SMD 0402; Manufacturer: YAGEO; Manufacturer Part Number: CC0402KRX7R7BB103
footprint CAP-0402 (0402 (1005M) Capacitor)
pins: 1, 2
